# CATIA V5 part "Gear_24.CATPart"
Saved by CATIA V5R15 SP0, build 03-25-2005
Part number: Gear_24
Material "Gold Metal": density 7860 kg/m3, Young's modulus 2e+11 Pa, Poisson ratio 0.266
Bounding box of the stored display mesh (mm): x -5 to 71, y -127 to 127, z -127 to 127
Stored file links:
  E:\#01 CATIA Lecture Materials\#06 DMU\#11 DMU Page01 KIN EX11\Gear_24.CATPart
  D:\공학과제\모델링\Part1.CATPart
  C:\Program Files\Dassault Systemes\B20\win_b64\startup\materials\Catalog.CATMaterial
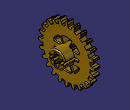
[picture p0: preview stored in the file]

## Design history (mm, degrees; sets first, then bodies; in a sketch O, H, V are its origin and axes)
Body1 (main body), material "Gold Metal"
  Sketch1, origin (16.5, 0, 0), H (0, 1, 0), V (0, 0, 1), geometry linked from another document
  Sketch2 on yz-plane, origin (0, 0, 0), H (0, 1, 0), V (0, 0, 1)
    projected line E1 (-9.25, 9.65) -> (-23.8, 9.65) from edge of Sketch1
    point P1 (-9.25, 9.65)
    point P2 (-23.8, 9.65)
    projected line E2 (-23.8, -8.85) -> (-9.25, -8.85) from edge of Sketch1
    point P3 (-23.8, -8.85)
    projected line E3 (-23.8, 9.65) -> (-23.8, -8.85) from edge of Sketch1
    point P5 (-23.8, 9.65)
    point P6 (-23.8, -8.85)
    projected line E4 (23.8, -8.85) -> (23.8, 9.65) from edge of Sketch1
    point P7 (23.8, -8.85)
    point P8 (23.8, 9.65)
    projected line E5 (9.25, -8.85) -> (23.8, -8.85) from edge of Sketch1
    point P10 (23.8, -8.85)
    projected line E6 (23.8, 9.65) -> (9.25, 9.65) from edge of Sketch1
    point P11 (23.8, 9.65)
    line L1 (-9.25, 23.8) -> (9.25, 23.8)
    line L2 (-9.25, 23.8) -> (-9.25, 9.65)
    point P15 (-9.25, 9.65)
    line L3 (9.25, 23.8) -> (9.25, 9.65)
    reference projected point E7 (-9.25, 9.65) from vertex [element of Sketch1 | element of Sketch1]
    line L4 (-9.25, -23.8) -> (9.25, -23.8)
    reference projected line E8 (9.25, -95.2) -> (-9.25, -95.2) from edge of Sketch1
    reference projected line E9 (-9.25, -142.8) -> (9.25, -142.8) from edge of Sketch1
    line L5 (-9.25, -8.85) -> (-9.25, -23.8)
    line L6 (9.25, -8.85) -> (9.25, -23.8)
    distance L4 L1 = 47.6 {= Sketch2.distance(E8 E9)}
    distance E8 E9 = 47.6 (reference)
    horizontal: L1 H, L4 H
    coincidence: L2 P1, P15 E7, P1 P15, P2 P5, P3 P6, P7 P10, P8 P11
    parallelism: L3 L2
    vertical: L2 V, L5 V, L6 V
    symmetry: L4 L1 H
  Sketch3 on yz-plane, origin (0, 0, 0), H (0, 1, 0), V (0, 0, 1)
    circle A1 centre (0, 0) radius 107.5
    radius A1 = 107.5
  Pad1: profile Sketch3, direction (1, 0, 0), length 26.5
  Body2
    Sketch4 on yz-plane, origin (0, 0, 0), H (0, 1, 0), V (0, 0, 1)
      construction circle A1 centre (0, 0) radius 127
      construction line L1 (0, 0) -> (-10.9243, 166.6733)
      construction line L2 (0, 0) -> (10.8518, 165.5664)
      construction line L3 (0, 0) -> (-34.856, 175.2332)
      line L4 (-7.0308, 107.2698) -> (-7.0308, 117.9306)
      line L5 (-7.0308, 117.9306) -> (-4.2168, 125.6622)
      point P6 (-3.75, 126.9446)
      arc A2 centre (0, 0) radius 127 from (-2.3748, 126.9778) to (2.3748, 126.9778) cw
      point P7 (0, 0)
      point P8 (0, 127)
      point P9 (3.75, 126.9446)
      line L6 (4.2168, 125.6622) -> (7.0308, 117.9306)
      line L7 (7.0308, 117.9306) -> (7.0308, 107.2698)
      point P11 (7.0308, 107.2698)
      arc A3 centre (0, 0) radius 107.5 from (7.0308, 107.2698) to (-7.0308, 107.2698) ccw
      reference projected circle E1 centre (0, 0) radius 107.5 from edge [face of Pad1 from Sketch3.A1 | end face of Pad1]
      reference projected circle E2 centre (0, 0) radius 107.5 from edge [face of Pad1 from Sketch3.A1 | end face of Pad1]
      axis line L8 (-7.0308, 117.9306) -> (7.0308, 117.9306)
      arc A4 centre (-2.3374, 124.9781) radius 2 from (-2.3748, 126.9778) to (-4.2168, 125.6622) ccw
      arc A5 centre (2.3374, 124.9781) radius 2 from (2.3748, 126.9778) to (4.2168, 125.6622) cw
      radius A1 = 127
      angle L1 L2 = 7.5
      angle L3 L1 = 7.5
      angle L5 L6 = 40
      distance P6 P9 = 7.5
      radius A4 = 2
      radius A5 = 2 {= Sketch4.radius(A4)}
      symmetry: L2 L1 V, L5 L6 V
      coincidence: A2 P8, P8 V, A3 E1, V P7, A2 A1, A3 E2, P11 L2, A2 P6, L5 P6, A2 P9, L6 P9
      vertical: L7 V, L4 V
      horizontal: L8 H
      tangency: A4 L5, A4 A2, A5 A2, A5 L6
    Pad2: profile Sketch4, direction (1, 0, 0), up to end face of Pad1
    CircPattern1: of Pad2, instances 24, angular step 15, axis from face of Pad1 from Sketch3.A1
  Add1: tool Body2
  Sketch5 on face of Pad1, origin (0, 0, 0), H (0, -1, 0), V (0, 0, 1)
    circle A1 centre (0, 0) radius 37.5
    radius A1 = 37.5
  Pad3: profile Sketch5, direction (1, 0, 0), length 71, opposite side length 5
  Pocket1: profile Sketch2, direction (-1, 0, 0), length 77.2, mirrored extent
  Sketch6 on face of Pad3, origin (0, 0, 0), H (0, -1, 0), V (0, 0, 1)
    line L1 (-53.5, 5) -> (53.5, 5)
    line L2 (53.5, 5) -> (53.5, -5)
    line L3 (53.5, -5) -> (-53.5, -5)
    line L4 (-53.5, -5) -> (-53.5, 5)
    distance L4 L2 = 107
    distance L3 L1 = 10
    horizontal: L1 H, L3 H
    vertical: L2 V, L4 V
    symmetry: L4 L2 V, L3 L1 H
  Pocket2: profile Sketch6, direction (1, 0, 0), length 77.2, mirrored extent
  Sketch7 on face of Pad3, origin (0, 0, 0), H (0, -1, 0), V (0, 0, 1)
    circle A1 centre (0, 0) radius 100
    circle A2 centre (0, 0) radius 78.5
    radius A2 = 78.5
    radius A1 = 100
  Pad4: profile Sketch7, direction (-1, 0, 0), length 5
  Sketch8 on face of Pad1, origin (0, 0, 0), H (0, -1, 0), V (0, 0, 1)
    arc A1 centre (0, 0) radius 65 from (58.8876, 27.5183) to (32.5, 56.2917) ccw
    arc A2 centre (0, 0) radius 37.5 from (12.8258, 35.2385) to (-12.8258, 35.2385) ccw
    reference projected circle E1 centre (0, 0) radius 37.5 from edge [face of Pad3 from Sketch5.A1 | start face of Pad3]
    point P1 (-22.2313, 61.08)
    line L1 (-22.2313, 61.08) -> (-12.8258, 35.2385)
    line L2 (12.8258, 35.2385) -> (22.2313, 61.08)
    point P2 (22.2313, 61.08)
    line L3 (-18.75, 32.476) -> (-32.5, 56.2917)
    point P3 (-32.5, 56.2917)
    line L4 (18.75, 32.476) -> (32.5, 56.2917)
    line L5 (-58.8876, 27.5183) -> (-25.4754, 27.5183)
    line L6 (25.4754, 27.5183) -> (58.8876, 27.5183)
    point P7 (-12.8258, 35.2385)
    arc A3 centre (0, 0) radius 65 from (22.2313, 61.08) to (-22.2313, 61.08) ccw
    arc A4 centre (0, 0) radius 65 from (-32.5, 56.2917) to (-58.8876, 27.5183) ccw
    point P10 (-25.4754, 27.5183)
    point P11 (-18.75, 32.476)
    point P12 (25.4754, 27.5183)
    arc A5 centre (0, 0) radius 37.5 from (-18.75, 32.476) to (-25.4754, 27.5183) ccw
    arc A6 centre (0, 0) radius 37.5 from (25.4754, 27.5183) to (18.75, 32.476) ccw
    radius A1 = 65
    distance L5 H = 27.5183
    angle L1 L2 = 40
    angle L3 L4 = 60
    distance P11 H = 32.476
    distance P7 H = 35.2385
    coincidence: A2 E1, P1 A1, P2 A1, P3 A1, L5 L6, A1 A3, A3 A4, A2 P10, A2 P11, A2 P12, A2 A5, A5 A6
    horizontal: L5 H, L6 H
    symmetry: L2 L1 V, L3 L4 V
  Pocket3: profile Sketch8, direction (1, 0, 0), through (limit type 6)
  Mirror1: of Pocket3, about xy-plane
  Fillet1: radius 5, on edge [end face of Pad4 | face of Pad4 from Sketch7.A2]; edge [face of Pad4 from Sketch7.A1 | end face of Pad4]; edge [face of Pad1 | face of Pad4 from Sketch7.A1]; edge [face of Pad4 from Sketch7.A2 | face of Pad1]; edge [face of Mirror1 | start face of Pad3]; edge [face of Pocket3 | start face of Pad3]; edge [end face of Pad3 | face of Pocket3]; edge [end face of Pad3 | face of Mirror1]
  Fillet2: radius 3, on face of Mirror1 (x9); face of Pocket3 from Sketch8.A4; face of Pocket3 from Sketch8.A3; face of Pocket3 from Sketch8.A1; face of Pocket3 from Sketch8.L4; face of Pocket3 from Sketch8.L3; face of Pocket3 from Sketch8.L1; face of Pocket3 from Sketch8.L5; face of Pocket3 from Sketch8.L6
  Fillet3: radius 2, on edge [face of Pocket1 from Sketch2.E5 | face of Pocket1 from Sketch2.L6]; face of Pocket1 from Sketch2.E5; face of Pocket2 from Sketch6.L3 (x2); face of Pocket1 from Sketch2.E6; face of Pocket2 from Sketch6.L1 (x2); face of Pocket1 from Sketch2.L1; face of Pocket1 from Sketch2.E1; face of Pocket2 from Sketch6.L2; face of Pocket1 from Sketch2.E2; face of Pocket1 from Sketch2.E3 (x2); face of Pocket1 from Sketch2.L5; face of Pocket1 from Sketch2.L4; face of Pocket1 from Sketch2.L3; face of Pocket1 from Sketch2.L2; face of Pocket2 from Sketch6.L4; face of Pocket1 from Sketch2.E4 (x2); face of Pocket1 from Sketch2.L6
